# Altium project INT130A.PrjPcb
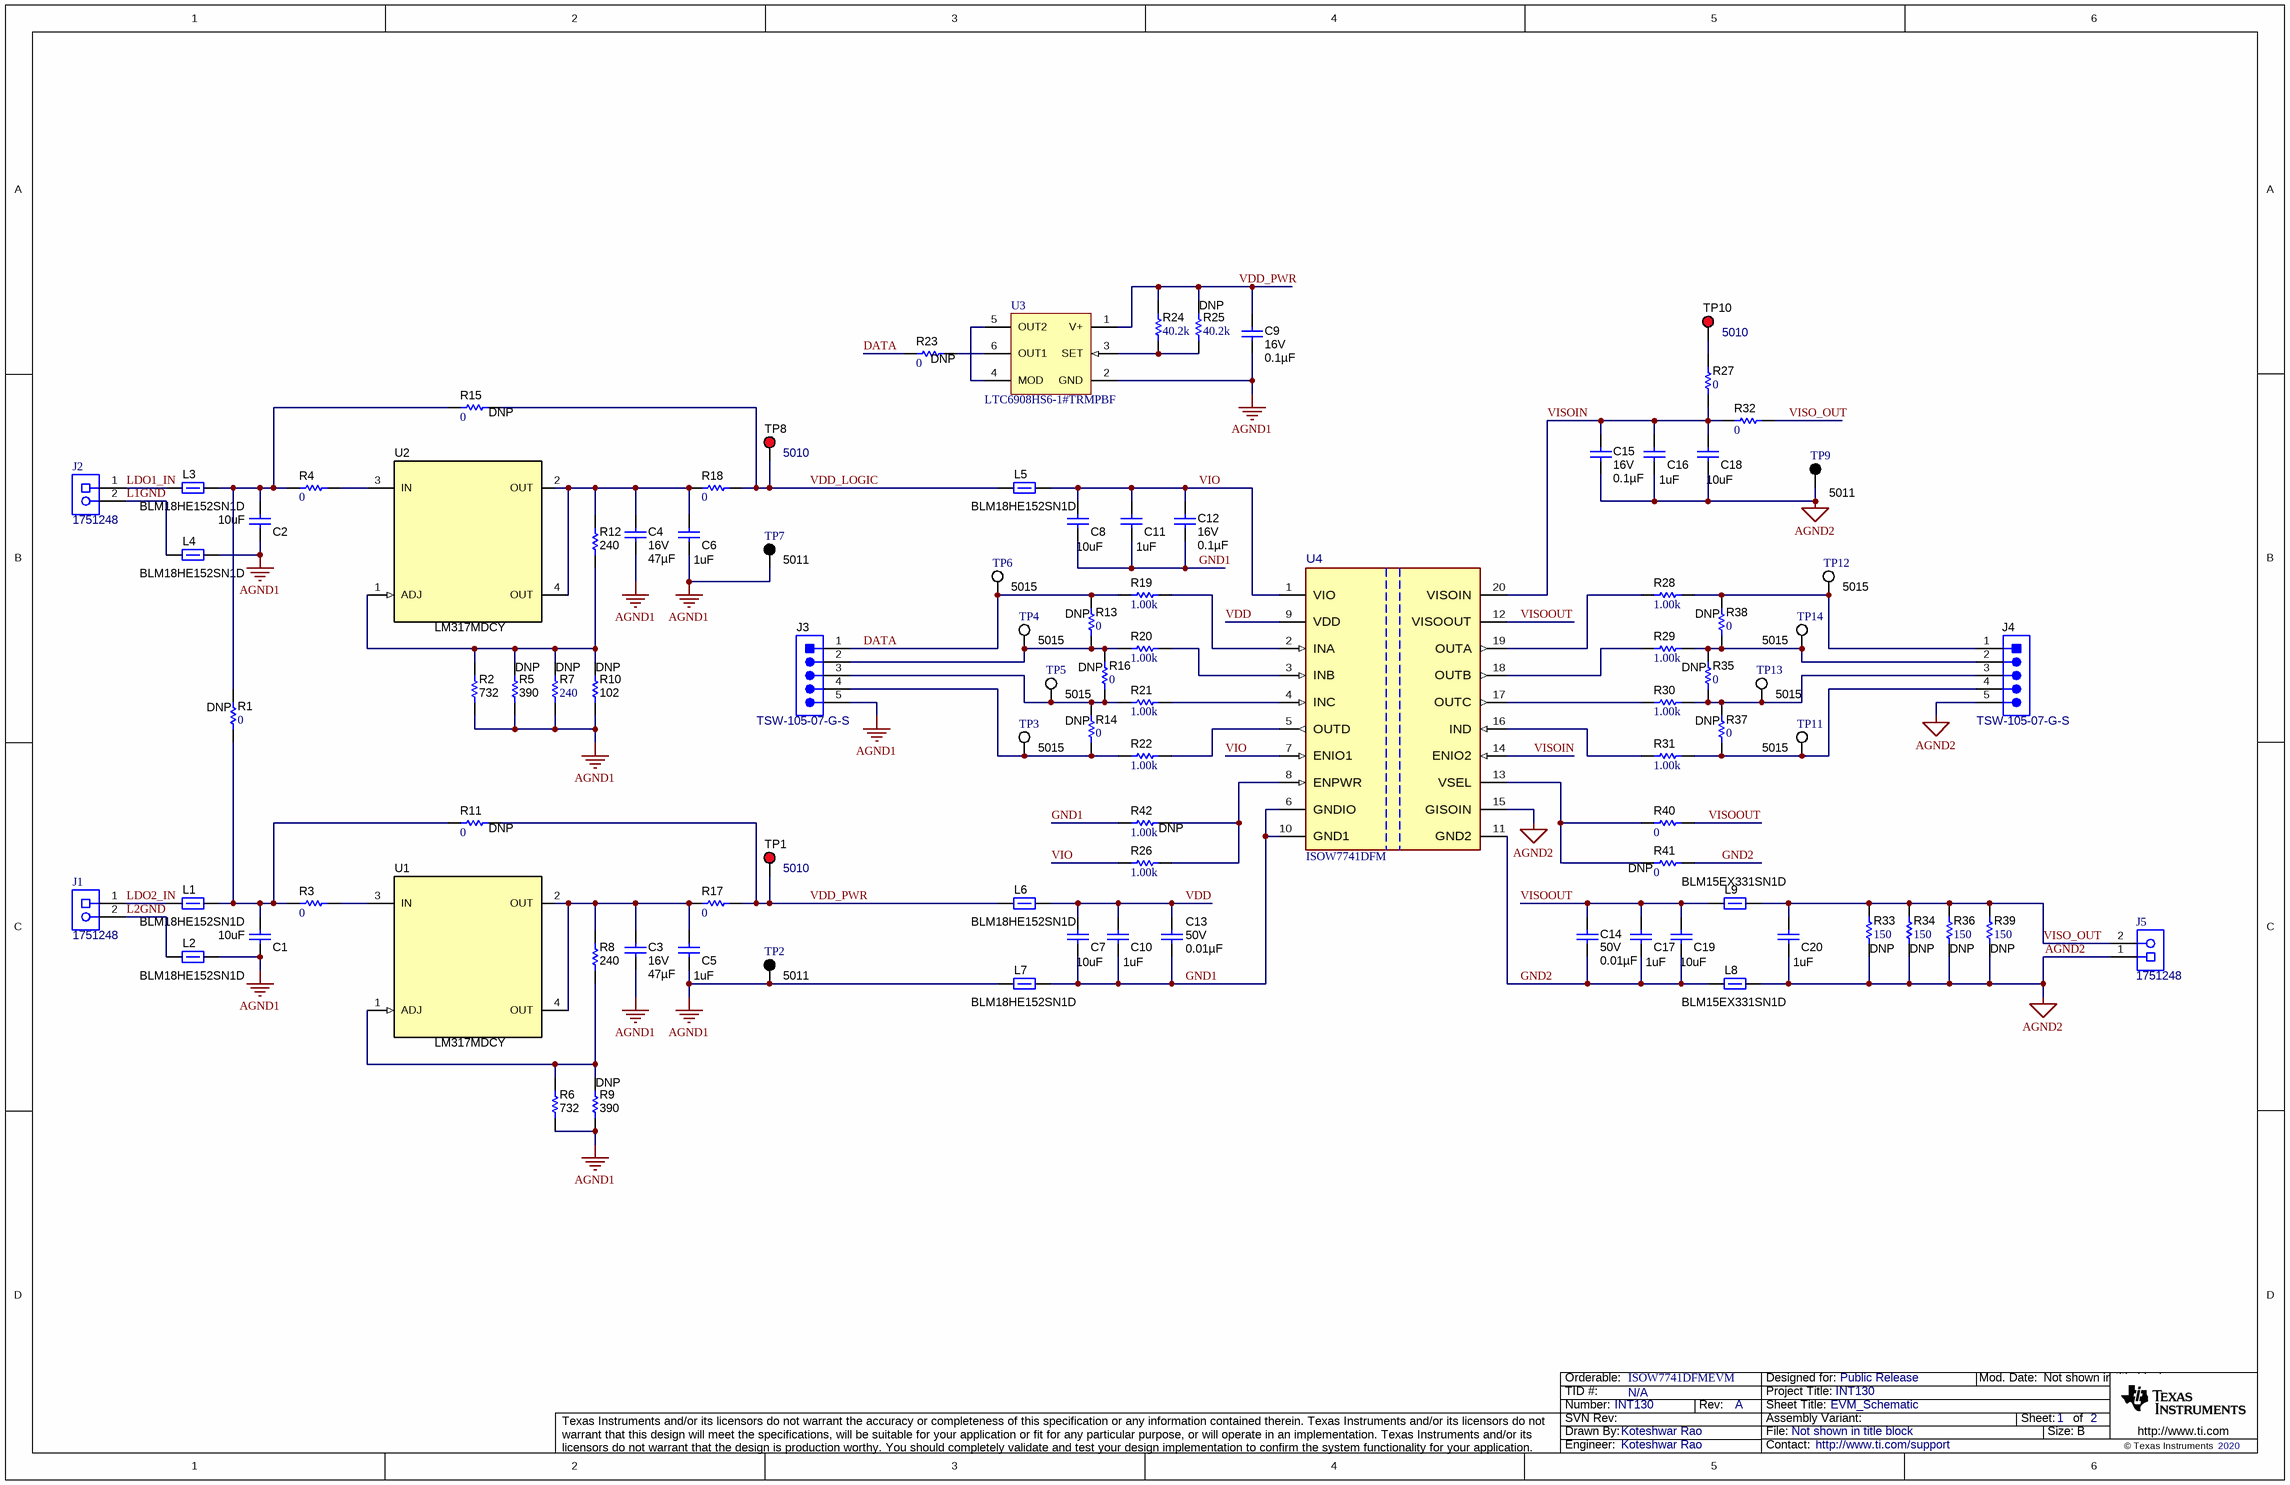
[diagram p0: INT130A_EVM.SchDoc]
CopyrightYear: 2020; Orderable: ISOW7741DFMEVM; PCB_Layout: Koteshwar Rao; PCB_Rev: A; PRJ_Customer: Public Release; PRJ_Engineer: Koteshwar Rao; PRJ_Number: INT130; PRJ_Title: INT130; SCH_Rev: A; TechSupport: http://www.ti.com/support; TID: N/A
2 sheets, 111 parts. Net scope: global (net labels, ports and power ports of the same name join across sheets).
Board file: INT130A.PcbDoc
Sheets:
  INT130A_EVM.SchDoc
  INT130A_Hardware.SchDoc

## Sheet INT130A_EVM.SchDoc: EVM_Schematic
size 431 x 279 mm; Date: Not shown in title block; ApprovedBy: Not shown in title block; CheckedBy: Not shown in title block; Author: Not shown in title block; CompanyName: Not shown in title block; DrawnBy: Koteshwar Rao; Engineer: Not shown in title block; Organization: Not shown in title block; Address1: Not shown in title block; Address2: Not shown in title block; Address3: Not shown in title block; Address4: Not shown in title block; DocumentNumber: 1; Revision: Use project parameter SCH_Rev; SheetNumber: 1; SheetTotal: 2; PageSetup: Record=PageOptions¦CenterHorizontal=True¦CenterVertical=True¦PrintScale=0.64¦XCorrection=1.00¦YCorrection=1.00¦PrintKind=0¦BorderSize=5000000¦LeftOffset=0¦BottomOffset=0¦Orientation=2¦PaperLength=1000¦PaperWidth=1000¦Scale=100¦PaperSource=15¦PrintQuality=600¦MediaType=1¦DitherType=10¦PrintScaleMode=1¦PaperKind=Letter; Orderable: ISOW7741DFMEVM

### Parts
C1  ValueDisplayed: 10uF  [0805_HV]  (hidden comment: GRM21BR6YA106KE43L)
C2  ValueDisplayed: 10uF  [0805_HV]  (hidden comment: GRM21BR6YA106KE43L)
C3  VDC_V: 16V  ValueDisplayed: 47µF  [1210_270]  (hidden comment: CL32A476KOJNNNE)
C4  VDC_V: 16V  ValueDisplayed: 47µF  [1210_270]  (hidden comment: CL32A476KOJNNNE)
C5  ValueDisplayed: 1uF  [0603]  (hidden comment: CL10A105KA8NNNC)
C6  ValueDisplayed: 1uF  [0603]  (hidden comment: CL10A105KA8NNNC)
C7  ValueDisplayed: 10uF  [0805_HV]  (hidden comment: GRM21BR6YA106KE43L)
C8  ValueDisplayed: 10uF  [0805_HV]  (hidden comment: GRM21BR6YA106KE43L)
C9  VDC_V: 16V  ValueDisplayed: 0.1µF  [0402]  (hidden comment: CL05B104KO5NNNC)
C10  ValueDisplayed: 1uF  [0603]  (hidden comment: CL10A105KA8NNNC)
C11  ValueDisplayed: 1uF  [0603]  (hidden comment: CL10A105KA8NNNC)
C12  VDC_V: 16V  ValueDisplayed: 0.1µF  [0402]  (hidden comment: CL05B104KO5NNNC)
C13  VDC_V: 50V  ValueDisplayed: 0.01µF  [0402]  (hidden comment: 0402B103K500CT)
C14  VDC_V: 50V  ValueDisplayed: 0.01µF  [0402]  (hidden comment: 0402B103K500CT)
C15  VDC_V: 16V  ValueDisplayed: 0.1µF  [0402]  (hidden comment: CL05B104KO5NNNC)
C16  ValueDisplayed: 1uF  [0603]  (hidden comment: CL10A105KA8NNNC)
C17  ValueDisplayed: 1uF  [0603]  (hidden comment: CL10A105KA8NNNC)
C18  ValueDisplayed: 10uF  [0805_HV]  (hidden comment: GRM21BR6YA106KE43L)
C19  ValueDisplayed: 10uF  [0805_HV]  (hidden comment: GRM21BR6YA106KE43L)
C20  ValueDisplayed: 1uF  [0603]  (hidden comment: CL10A105KA8NNNC)
J1  1751248  [CONN_1751248]
J2  1751248  [CONN_1751248]
J3  TSW-105-07-G-S  [TSW-105-07-X-S]
J4  TSW-105-07-G-S  [TSW-105-07-X-S]
J5  1751248  [CONN_1751248]
L1  BLM18HE152SN1D  [0603]
L2  BLM18HE152SN1D  [0603]
L3  BLM18HE152SN1D  [0603]
L4  BLM18HE152SN1D  [0603]
L5  BLM18HE152SN1D  [0603]
L6  BLM18HE152SN1D  [0603]
L7  BLM18HE152SN1D  [0603]
L8  BLM15EX331SN1D  [0402]
L9  BLM15EX331SN1D  [0402]
R1  DNP  ValueDisplayed: 0  [0603]
R2  ValueDisplayed: 732  [0603]  (hidden comment: RC0603FR-07732RL)
R3  ValueDisplayed: 0  [0603]  (hidden comment: RC0603JR-070RL)
R4  ValueDisplayed: 0  [0603]  (hidden comment: RC0603JR-070RL)
R5  DNP  ValueDisplayed: 390  [0603]
R6  ValueDisplayed: 732  [0603]  (hidden comment: RC0603FR-07732RL)
R7  DNP  ValueDisplayed: 240  [0603]
R8  ValueDisplayed: 240  [0603]  (hidden comment: RC0603FR-07240RL)
R9  DNP  ValueDisplayed: 390  [0603]
R10  DNP  ValueDisplayed: 102  [0603]
R11  DNP  ValueDisplayed: 0  [0603]
R12  ValueDisplayed: 240  [0603]  (hidden comment: RC0603FR-07240RL)
R13  DNP  ValueDisplayed: 0  [0603]
R14  DNP  ValueDisplayed: 0  [0603]
R15  DNP  ValueDisplayed: 0  [0603]
R16  DNP  ValueDisplayed: 0  [0603]
R17  ValueDisplayed: 0  [0603]  (hidden comment: RC0603JR-070RL)
R18  ValueDisplayed: 0  [0603]  (hidden comment: RC0603JR-070RL)
R19  ValueDisplayed: 1.00k  [0603]  (hidden comment: RC0603FR-071KL)
R20  ValueDisplayed: 1.00k  [0603]  (hidden comment: RC0603FR-071KL)
R21  ValueDisplayed: 1.00k  [0603]  (hidden comment: RC0603FR-071KL)
R22  ValueDisplayed: 1.00k  [0603]  (hidden comment: RC0603FR-071KL)
R23  DNP  ValueDisplayed: 0  [0603]
R24  ValueDisplayed: 40.2k  [0603]  (hidden comment: RC0603FR-0740K2L)
R25  DNP  ValueDisplayed: 40.2k  [0603]
R26  ValueDisplayed: 1.00k  [0402]  (hidden comment: RC0402FR-071KL)
R27  ValueDisplayed: 0  [0603]  (hidden comment: RC0603JR-070RL)
R28  ValueDisplayed: 1.00k  [0603]  (hidden comment: RC0603FR-071KL)
R29  ValueDisplayed: 1.00k  [0603]  (hidden comment: RC0603FR-071KL)
R30  ValueDisplayed: 1.00k  [0603]  (hidden comment: RC0603FR-071KL)
R31  ValueDisplayed: 1.00k  [0603]  (hidden comment: RC0603FR-071KL)
R32  ValueDisplayed: 0  [0603]  (hidden comment: RC0603JR-070RL)
R33  DNP  ValueDisplayed: 150  [1206]
R34  DNP  ValueDisplayed: 150  [1206]
R35  DNP  ValueDisplayed: 0  [0603]
R36  DNP  ValueDisplayed: 150  [1206]
R37  DNP  ValueDisplayed: 0  [0603]
R38  DNP  ValueDisplayed: 0  [0603]
R39  DNP  ValueDisplayed: 150  [1206]
R40  ValueDisplayed: 0  [0402]  (hidden comment: RC0402JR-070RL)
R41  DNP  ValueDisplayed: 0  [0402]
R42  DNP  ValueDisplayed: 1.00k  [0402]
TP1  5010  [KSTN-5010_V]
TP2  5011  [Keystone5011]
TP3  5015  [Testpoint_Keystone_Miniature]
TP4  5015  [Testpoint_Keystone_Miniature]
TP5  5015  [Testpoint_Keystone_Miniature]
TP6  5015  [Testpoint_Keystone_Miniature]
TP7  5011  [Keystone5011]
TP8  5010  [KSTN-5010_V]
TP9  5011  [Keystone5011]
TP10  5010  [KSTN-5010_V]
TP11  5015  [Testpoint_Keystone_Miniature]
TP12  5015  [Testpoint_Keystone_Miniature]
TP13  5015  [Testpoint_Keystone_Miniature]
TP14  5015  [Testpoint_Keystone_Miniature]
U1  LM317MDCY  [DCY0004A_N]
U2  LM317MDCY  [DCY0004A_N]
U3  LTC6908HS6-1#TRMPBF  [LT-S6-6-SOT-23_L]
U4  ISOW7741DFM  [DFM0020A-MFG]

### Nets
AGND1: C1.2 C2.2 C3.2 C4.2 C5.2 C6.2 C9.2 J3.5 L2.2 L4.2 L7.1 R2.1 R5.1 R6.1 R7.1 R9.1 R10.1 TP2.1 TP7.1 U3.2(GND)
AGND2: C15.2 C16.2 C18.2 C20.2 J4.5 J5.1 L8.2 R33.1 R34.1 R36.1 R39.1 TP9.1 U4.15(GISOIN)
DATA: J3.1 R13.2 R19.1 R23.1 TP6.1
GND1: C7.2 C8.2 C10.2 C11.2 C12.2 C13.1 L7.2 R42.1 U4.6(GNDIO) U4.10(GND1)
GND2: C14.2 C17.2 C19.2 L8.1 R41.2 U4.11(GND2)
L1GND: J2.2 L4.1
L2GND: J1.2 L2.1
LDO1_IN: J2.1 L3.1
LDO2_IN: J1.1 L1.1
VDD: C7.1 C10.1 C13.2 L6.2 U4.9(VDD)
VDD_LOGIC: L5.1 R15.2 R18.2 TP8.1
VDD_PWR: C9.1 L6.1 R11.2 R17.2 R24.2 R25.2 TP1.1 U3.1(V+)
VIO: C8.1 C11.1 C12.1 L5.2 R26.1 U4.1(VIO) U4.7(ENIO1)
VISO_OUT: C20.1 J5.2 L9.2 R32.2 R33.2 R34.2 R36.2 R39.2
VISOIN: C15.1 C16.1 C18.1 R27.1 R32.1 U4.14(ENIO2) U4.20(VISOIN)
VISOOUT: C14.1 C17.1 C19.1 L9.1 R40.2 U4.12(VISOOUT)
NetC1_1: C1.1 L1.2 R1.1 R3.1 R11.1
NetC2_1: C2.1 L3.2 R1.2 R4.1 R15.1
NetC3_1: C3.1 C5.1 R8.2 R17.1 U1.2(OUT) U1.4(OUT)
NetC4_1: C4.1 C6.1 R12.2 R18.1 U2.2(OUT) U2.4(OUT)
NetJ3_2: J3.2 R13.1 R16.2 R20.1 TP4.1
NetJ3_3: J3.3 R14.2 R16.1 R21.1 TP5.1
NetJ3_4: J3.4 R14.1 R22.1 TP3.1
NetJ4_1: J4.1 R28.2 R38.2 TP12.1
NetJ4_2: J4.2 R29.2 R35.2 R38.1 TP14.1
NetJ4_3: J4.3 R30.2 R35.1 R37.2 TP13.1
NetJ4_4: J4.4 R31.2 R37.1 TP11.1
NetR2_2: R2.2 R5.2 R7.2 R10.2 R12.1 U2.1(ADJ)
NetR3_2: R3.2 U1.3(IN)
NetR4_2: R4.2 U2.3(IN)
NetR6_2: R6.2 R8.1 R9.2 U1.1(ADJ)
NetR19_2: R19.2 U4.2(INA)
NetR20_2: R20.2 U4.3(INB)
NetR21_2: R21.2 U4.4(INC)
NetR22_2: R22.2 U4.5(OUTD)
NetR23_2: R23.2 U3.6(OUT1)
NetR24_1: R24.1 R25.1 U3.3(SET)
NetR26_2: R26.2 R42.2 U4.8(ENPWR)
NetR27_2: R27.2 TP10.1
NetR28_1: R28.1 U4.19(OUTA)
NetR29_1: R29.1 U4.18(OUTB)
NetR30_1: R30.1 U4.17(OUTC)
NetR31_1: R31.1 U4.16(IND)
NetR40_1: R40.1 R41.1 U4.13(VSEL)
NetU3_4: U3.4(MOD) U3.5(OUT2)

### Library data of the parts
C1 C2 C7 C8 C18 C19 = CMP-0008310-2: CAP, CERM, 10 uF, 35 V, +/- 10%, X5R, 0805; Manufacturer: MuRata; Polarized: N; Value: 10uF; U/M: EA; Cap_F: 10µF; Value1: Unknown; VDC_V: 35V; TaMin_C: -55°C; TaMax_C: 85°C; Cap_Case: 0805; AEC Category: Q200; SizeArea_mm2: 2.5; SizeAreaWB_mm2: 6.75; SizeX_mm: 2; SizeY_mm: 1.25; SizeZ_mm: 1.45
C3 C4 = CMP-0082097-1: CAP, CERM, 47 µF, 16 V,+/- 10%, X5R, 1210; Manufacturer: Samsung Electro-Mechanics; TaMin_C: -55°C; ESR_ohm: 1m; Polarized: N; SizeAreaWB_mm2: 14.7; Value1: 0.001 ohm; U/M: EA; Value: 47uF; TaMax_C: 85°C; SizeZ_mm: 2.7; SizeX_mm: 3.2; SizeY_mm: 2.5; Cap_Case: 1210; SizeArea_mm2: 8; IRMS_A: 6A
C5 C6 C10 C11 C16 C17 C20 = CMP-0007350-5: CAP, CERM, 1 uF, 50 V, +/- 10%, X5R, 0603; Manufacturer: Samsung Electro-Mechanics; Polarized: N; Value: 1uF; U/M: EA; Cap_F: 1µF; Value1: Unknown; VDC_V: 25V; TaMin_C: -55°C; TaMax_C: 85°C; AEC Category: NA; SizeArea_mm2: 1.28; SizeAreaWB_mm2: 4.68; SizeX_mm: 1.6; SizeY_mm: 0.8; SizeZ_mm: 1
C9 C12 C15 = CMP-0085850-1: CAP, CERM, 0.1 µF, 16 V,+/- 10%, X7R, 0402; Manufacturer: Walsin; SizeZ_mm: 0.6; SizeX_mm: 1; AEC Category: Q200; AEC Qualified: N; SizeY_mm: 0.5; Value: 0.1uF; Cap_F: 100nF; U/M: EA; SizeAreaWB_mm2: 3; TaMin_C: -55°C; TaMax_C: 125°C
C13 C14 = CMP-0085842-1: CAP, CERM, 0.01 µF, 50 V,+/- 10%, X7R, 0402; Manufacturer: Walsin; AEC Qualified: N; SizeZ_mm: 0.6; U/M: EA; Value: 0.01uF; TaMax_C: 125°C; AEC Category: Q200; SizeY_mm: 0.5; Cap_F: 10nF; SizeAreaWB_mm2: 3; TaMin_C: -55°C; SizeX_mm: 1
J1 J2 J5 = CMP-0055473-1: Conn Term Block, 2POS, 3.5mm, TH; Manufacturer: Phoenix Contact; CNHeader: FALSE; Green_Lifecycle: Not Set; Green_REACh: Incomplete; CompType: Terminal Block; CT: TRUE
J3 J4 = CMP-0075411-1: Header, 100mil, 5x1, Gold, TH; Manufacturer: Samtec; Pitch_mm: 2.54; Cert_VDE: N; Gender: Male; Cert_CSA: Y; Voltage_V: 550V; Green_REACh: Passed; Current_A: 6.3A; CT: False; Green_Lifecycle: Active; Row_Count: 1; CNHeader: True
L1-L7 = CMP-0003349-2: Ferrite Bead, 1500 ohm @ 100 MHz, 0.5 A, 0603; Manufacturer: MuRata; Ztyp@1GHz_Ohm: 1.5k; SizeAreaWB_mm2: 4.68; DCR_ohm: 5d; Value1: 0.5 ohm; Imax_A: 5dA; SizeZ_mm: 1; SizeX_mm: 1.6; SizeY_mm: 0.8; Value2: 0.5A; SizeArea_mm2: 1.28
L8 L9 = CMP-0003421-1: Ferrite Bead, 330 ohm @ 100 MHz, 1.1 A, 0402; Manufacturer: MuRata; Ztyp@1GHz_Ohm: 550; ZTyp@100MHz_Ohm: 330; SizeAreaWB_mm2: 3; DCR_ohm: 0.28; Value1: 0.28 ohm; Value: 330 ohm; Imax_A: 1100mA; SizeZ_mm: 0.6; SizeX_mm: 1; SizeY_mm: 0.5; Value2: 1.1A
R1 R11 R13-R16 R23 R35 R37 R38 = CMP-0025885-5: RES, 0, 5%, 0.1 W, 0603; Manufacturer: Yageo; PartNumber: RC0603JR-070RL; Power_W: 100mW; TempCo: 200 ppm/C; Value_Code: 0000; Value: 0; EIA_Code: E24; SizeX_mm: 1.6; SizeZ_mm: 1; Value2: 0.1W; SizeArea_mm2: 1.28; AEC Qualified: N; VDC_V: 75V; AEC Category: Q200; SizeY_mm: 0.8; SizeAreaWB_mm2: 4.68
R2 R6 = CMP-0023262-5: RES, 732, 1%, 0.1 W, 0603; Manufacturer: Yageo; Power_W: 100mW; TempCo: 100 ppm/C; Value_Code: 732R; Value: 732; EIA_Code: E96; SizeX_mm: 1.6; SizeY_mm: 0.8; SizeZ_mm: 1; Value2: 0.1W; SizeArea_mm2: 1.28; AEC Qualified: N; VDC_V: 75V; AEC Category: Q200; SizeAreaWB_mm2: 4.68
R3 R4 R17 R18 R27 R32 = CMP-0025885-5: RES, 0, 5%, 0.1 W, 0603; Manufacturer: Yageo; Power_W: 100mW; TempCo: 200 ppm/C; Value_Code: 0000; Value: 0; EIA_Code: E24; SizeX_mm: 1.6; SizeZ_mm: 1; Value2: 0.1W; SizeArea_mm2: 1.28; AEC Qualified: N; VDC_V: 75V; AEC Category: Q200; SizeY_mm: 0.8; SizeAreaWB_mm2: 4.68
R5 R9 = CMP-0023069-5: RES, 390, 1%, 0.1 W, 0603; Manufacturer: Yageo; PartNumber: RC0603FR-07390RL; Power_W: 100mW; TempCo: 100 ppm/C; Value_Code: 390R; Value: 390; SizeX_mm: 1.6; SizeY_mm: 0.8; SizeZ_mm: 1; Value2: 0.1W; SizeArea_mm2: 1.28; AEC Qualified: N; VDC_V: 75V; AEC Category: Q200; SizeAreaWB_mm2: 4.68
R7 = CMP-0022938-5: RES, 240, 1%, 0.1 W, 0603; Manufacturer: Yageo; PartNumber: RC0603FR-07240RL; Power_W: 100mW; TempCo: 100 ppm/C; Value_Code: 240R; Value: 240; SizeX_mm: 1.6; SizeY_mm: 0.8; SizeZ_mm: 1; Value2: 0.1W; SizeArea_mm2: 1.28; AEC Qualified: N; VDC_V: 75V; AEC Category: Q200; SizeAreaWB_mm2: 4.68
R8 R12 = CMP-0022938-5: RES, 240, 1%, 0.1 W, 0603; Manufacturer: Yageo; Power_W: 100mW; TempCo: 100 ppm/C; Value_Code: 240R; Value: 240; SizeX_mm: 1.6; SizeY_mm: 0.8; SizeZ_mm: 1; Value2: 0.1W; SizeArea_mm2: 1.28; AEC Qualified: N; VDC_V: 75V; AEC Category: Q200; SizeAreaWB_mm2: 4.68
R10 = CMP-0022738-5: RES, 102, 1%, 0.1 W, 0603; Manufacturer: Yageo; PartNumber: RC0603FR-07102RL; Power_W: 100mW; TempCo: 100 ppm/C; Value_Code: 102R; Value: 102; EIA_Code: E96; SizeX_mm: 1.6; SizeY_mm: 0.8; SizeZ_mm: 1; Value2: 0.1W; SizeArea_mm2: 1.28; AEC Qualified: N; VDC_V: 75V; AEC Category: Q200; SizeAreaWB_mm2: 4.68
R19-R22 R28-R31 = CMP-0022895-5: RES, 1.00 k, 1%, 0.1 W, 0603; Manufacturer: Yageo; Power_W: 100mW; TempCo: 100 ppm/C; Value_Code: 1k00; Value: 1.00k; EIA_Code: E96; Res_ohm: 1k; SizeX_mm: 1.6; SizeY_mm: 0.8; SizeZ_mm: 1; Value2: 0.1W; SizeArea_mm2: 1.28; AEC Qualified: N; VDC_V: 75V; AEC Category: Q200; SizeAreaWB_mm2: 4.68
R24 = CMP-0023098-5: RES, 40.2 k, 1%, 0.1 W, 0603; Manufacturer: Yageo; Power_W: 100mW; TempCo: 100 ppm/C; Value_Code: 40k2; Value: 40.2k; EIA_Code: E96; SizeX_mm: 1.6; SizeY_mm: 0.8; SizeZ_mm: 1; Value2: 0.1W; SizeArea_mm2: 1.28; AEC Qualified: N; VDC_V: 75V; AEC Category: Q200; SizeAreaWB_mm2: 4.68
R25 = CMP-0023098-5: RES, 40.2 k, 1%, 0.1 W, 0603; Manufacturer: Yageo; PartNumber: RC0603FR-0740K2L; Power_W: 100mW; TempCo: 100 ppm/C; Value_Code: 40k2; Value: 40.2k; EIA_Code: E96; SizeX_mm: 1.6; SizeY_mm: 0.8; SizeZ_mm: 1; Value2: 0.1W; SizeArea_mm2: 1.28; AEC Qualified: N; VDC_V: 75V; AEC Category: Q200; SizeAreaWB_mm2: 4.68
R26 = CMP-0026725-1: RES, 1.00 k, 1%, 0.0625 W, 0402; Manufacturer: Yageo America; Power_W: 62.5mW; TempCo: 100 ppm/C; Value_Code: 1k00; U/M: EA; Value: 1.00k; EIA_Code: E96; Res_ohm: 1k; SizeX_mm: 1; SizeY_mm: 0.5; SizeZ_mm: 0.6; AEC Qualified: N; VDC_V: 50V; AEC Category: Q200
R33 R34 R36 R39 = CMP-0018759-2: RES, 0, 5%, 0.25 W, 1206; Manufacturer: Yageo America; PartNumber: RC1206JR-070RL; Power_W: 250mW; TempCo: 200 ppm/C; Value_Code: 0000; U/M: EA; Value: 0; EIA_Code: E24; SizeX_mm: 3.2; SizeY_mm: 1.6; SizeZ_mm: 1.35; Value2: 0.25W; SizeArea_mm2: 5.12; VDC_V: 200V; AEC Category: Q200
R40 = CMP-0027004-2: RES, 0, 5%, 0.063 W, 0402; Manufacturer: Yageo America; Power_W: 63mW; TempCo: 200 ppm/C; Value_Code: 0000; U/M: EA; Value: 0; EIA_Code: E24; SizeX_mm: 1; SizeY_mm: 0.5; SizeZ_mm: 0.6; Value2: 0.063W; VDC_V: 50V; AEC Category: Q200
R41 = CMP-0027004-2: RES, 0, 5%, 0.063 W, 0402; Manufacturer: Yageo America; PartNumber: RC0402JR-070RL; Power_W: 63mW; TempCo: 200 ppm/C; Value_Code: 0000; U/M: EA; Value: 0; EIA_Code: E24; SizeX_mm: 1; SizeY_mm: 0.5; SizeZ_mm: 0.6; Value2: 0.063W; VDC_V: 50V; AEC Category: Q200
R42 = CMP-0026725-1: RES, 1.00 k, 1%, 0.0625 W, 0402; Manufacturer: Yageo America; PartNumber: RC0402FR-071KL; Power_W: 62.5mW; TempCo: 100 ppm/C; Value_Code: 1k00; U/M: EA; Value: 1.00k; EIA_Code: E96; Res_ohm: 1k; SizeX_mm: 1; SizeY_mm: 0.5; SizeZ_mm: 0.6; AEC Qualified: N; VDC_V: 50V; AEC Category: Q200
TP1 TP8 TP10 = CMP-1672-00002-3: Test Point, Red, Through Hole, RoHS, Bulk; Manufacturer: Keystone
TP2 TP7 TP9 = CMP-0055148-1: Test Point, Multipurpose, Black, TH; Manufacturer: Keystone; CNHeader: FALSE; Green_Lifecycle: Active; Green_REACh: Passed; ContactFinish: Silver; CT: TRUE
TP3-TP6 TP11-TP14 = CMP-0055152-1: Test Point, Miniature, SMT; Manufacturer: Keystone; CNHeader: FALSE; Green_Lifecycle: Active; Green_REACh: Passed; CT: TRUE
U1 U2 = CMP-0065981-1: 3/4 Pin 500mA Adjustable Positive Voltage Regulator, DCY0004A (SOT-223-4); Alternate Manufacturer: Texas Instruments; Green_Lifecycle: Active; SizeAreaWB_mm2: 76.5; Green_REACh: Passed; U/M: EA; SizeZ_mm: 1.8; SizeX_mm: 7.0; SizeY_mm: 6.5; SizeArea_mm2: 45.5; CompType: IC
U3 = CMP-0475-00317-1: Resistor Set SOT-23 Oscillator, 2.7 to 5.5 V, 6-pin SOT23 (S6-6), -40 to 85 degC, Pb-Free; Manufacturer: Linear Technology; Vin Min(V): 2.7; Voutput: 5V; Max Iout(mA): 40; Vin Max(V): 5.5; Ishutdown(uA): 0.01; Frequency(kHz): 700; Isupply(mA): 0.013
U4 = CMP-0091099-2: Manufacturer: Texas Instruments; Standoff Height: 0.1mm; CompType: IC; AEC Qualified: No; SizeZ_mm: 3.55mm; AEC Category: Q200

## Sheet INT130A_Hardware.SchDoc: Hardware Sheet
size 431 x 279 mm; Date: Not shown in title block; ApprovedBy: Not shown in title block; CheckedBy: Not shown in title block; Author: Not shown in title block; CompanyName: Not shown in title block; Engineer: Not shown in title block; Organization: Not shown in title block; Address1: Not shown in title block; Address2: Not shown in title block; Address3: Not shown in title block; Address4: Not shown in title block; DocumentNumber: 1; Revision: Use project parameter SCH_Rev; SheetNumber: 2; SheetTotal: 2; PageSetup: Record=PageOptions¦CenterHorizontal=True¦CenterVertical=True¦PrintScale=1.00¦XCorrection=1.00¦YCorrection=1.00¦PrintKind=0¦BorderSize=5000000¦LeftOffset=0¦BottomOffset=0¦Orientation=2¦PaperLength=1000¦PaperWidth=1000¦Scale=100¦PaperSource=15¦PrintQuality=600¦MediaType=1¦DitherType=10¦PaperKind=Letter¦PrintScaleMode=1
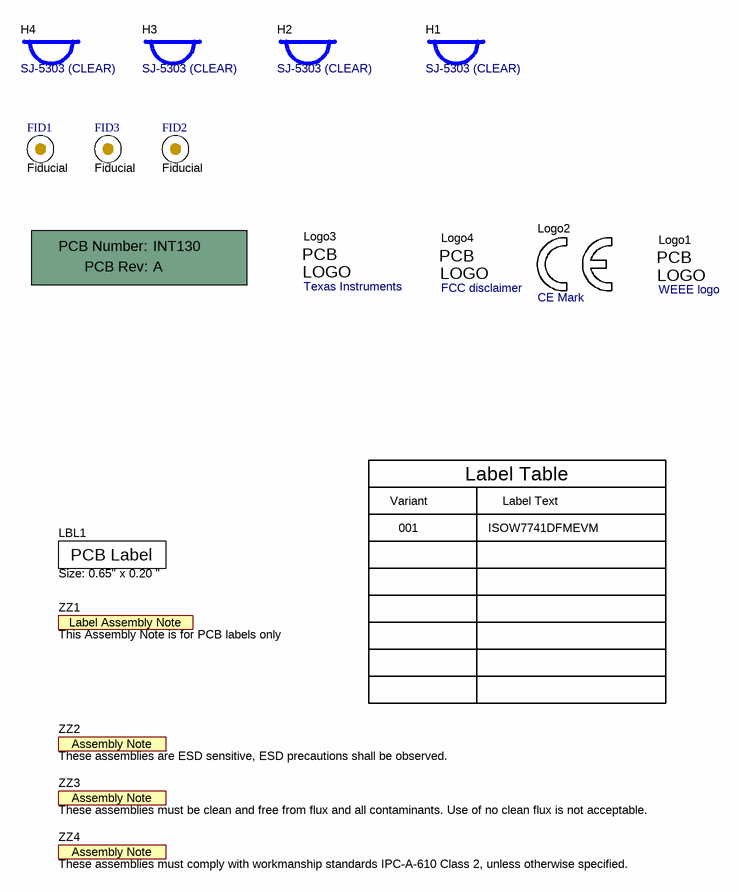
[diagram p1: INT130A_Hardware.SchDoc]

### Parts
!PCB1  Printed Circuit Board  (value not drawn)  (mechanical)
FID1  Fiducial  [Fiducial10-30]
FID2  Fiducial  [Fiducial10-30]
FID3  Fiducial  [Fiducial10-30]
H1  SJ-5303 (CLEAR)  [Bumpon_SJ5003Transparent]
H2  SJ-5303 (CLEAR)  [Bumpon_SJ5003Transparent]
H3  SJ-5303 (CLEAR)  [Bumpon_SJ5003Transparent]
H4  SJ-5303 (CLEAR)  [Bumpon_SJ5003Transparent]
LBL1  Size: 0.65" x 0.20 "  [Label_650x200]
Logo1  WEEE logo  [WEEE_Minimum]  (no BOM)
Logo2  CE Mark  [CE_Mark_5mm]  (no BOM)
Logo3  Texas Instruments  [TI_Horizontal_Overlay_Medium]  (no BOM)
Logo4  FCC disclaimer  [FCC_disclaimer]  (no BOM)
ZZ1  This Assembly Note is for PCB labels only  [AssemblyNoteLabel]  (no BOM)
ZZ2  These assemblies are ESD sensitive, ESD precautions shall be observed.  [AssemblyNote]  (no BOM)
ZZ3  These assemblies must be clean and free from flux and all contaminants. Use of no clean flux is not acceptable.  [AssemblyNote]  (no BOM)
ZZ4  These assemblies must comply with workmanship standards IPC-A-610 Class 2, unless otherwise specified.  [AssemblyNote]  (no BOM)

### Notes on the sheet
- Variant
- Label Table
- Label Text
- 001
- ISOW7741DFMEVM

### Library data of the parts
!PCB1 = PCB: Manufacturer: Any; PartNumber: INT130; SymbolCreator: a0412235
FID1-FID3 = CMP-0077181-1: Fiducial mark.  There is nothing to buy or mount.
H1-H4 = CMP-0003620-1: Bumpon, Hemisphere, 0.44 X 0.20, Clear; Manufacturer: 3M
LBL1 = THT-14-423-10: Thermal Transfer Printable Labels, 0.650" W x 0.200" H - 10,000 per roll; Manufacturer: Brady; SymbolCreator: a0412235; CompType: Label
Logo1 = CMP-0074769-1
Logo2 = CMP-0074844-1: SymbolCreator: a0412235
Logo3 = CMP-0074838-1: Texas Instrument Corporate Signature; SymbolCreator: a0412235; Lib Reference: TI_Logo
Logo4 = CMP-0074847-1: FCC_disclaimer
ZZ1 = AssemblyNoteLabel: SymbolCreator: a0412235
ZZ2-ZZ4 = AssemblyNote: SymbolCreator: codlsc

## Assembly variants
001: not fitted FID1 FID2 FID3 R1 R5 R7 R9 R10 R11 R13 R14 R15 R16 R23 R25 R33 R34 R35 R36 R37 R38 R39 R41 R42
